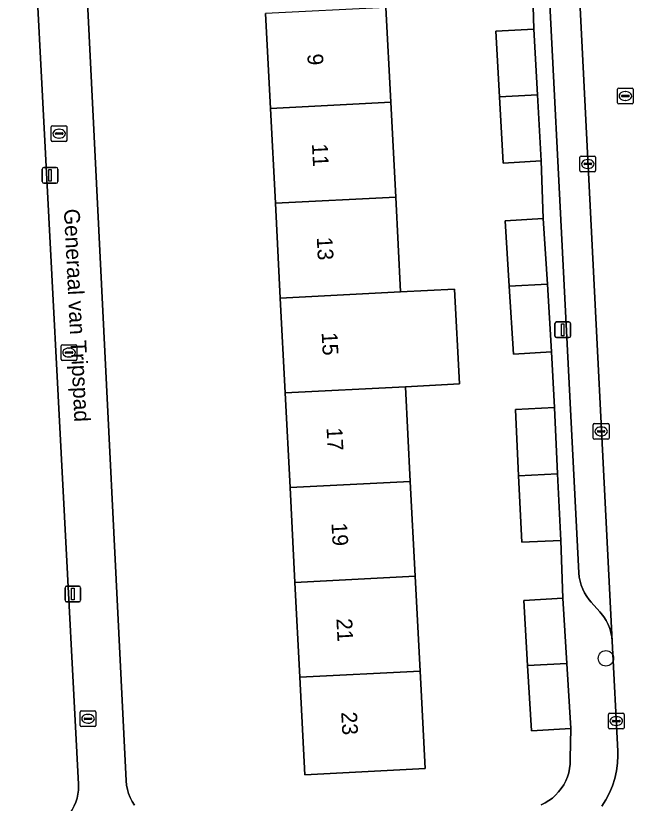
# Model space of a CAD drawing. Extents: x 161084 to 161928, y 385354 to 386522.
# Drawn here: x 161488.1 to 161527.4, y 385662.3 to 385712.5 of the extents above; entities that cross this region are included whole.
import ezdxf

# ---------------------------------------------------------------- set-up
doc = ezdxf.new("R2010")
doc.units = 0
for name, color, linetype in [('IMGEO_Boom', 7, 'Continuous'), ('IMGEO_Erf', 7, 'Continuous'), ('IMGEO_Kolk', 7, 'Continuous'), ('IMGEO_Lichtmast', 7, 'Continuous'), ('IMGEO_Openbare_ruimte_label', 7, 'Continuous'), ('IMGEO_Pand', 7, 'Continuous'), ('IMGEO_Pand_nummerreeks', 7, 'Continuous'), ('IMGEO_Parkeervlak_open', 7, 'Continuous'), ('IMGEO_Rijbaan_lokaal_open', 7, 'Continuous'), ('IMGEO_Rioolput', 7, 'Continuous'), ('IMGEO_Voetpad_open', 7, 'Continuous')]:
    doc.layers.add(name, color=color, linetype=linetype)

msp = doc.modelspace()

# ---------------------------------------------------------------- linework, layer by layer
at = {"layer": 'IMGEO_Boom'}
msp.add_circle((161525.652, 385671.57), 0.489, dxfattribs=at)
at = {"layer": 'IMGEO_Erf'}
for points in [[(161479.748, 385659.941), (161489.33, 385660.501), (161489.589, 385660.528), (161489.844, 385660.578), (161490.094, 385660.65), (161490.336, 385660.745), (161490.569, 385660.86), (161490.79, 385660.996), (161490.999, 385661.152), (161491.193, 385661.325), (161491.37, 385661.515), (161491.53, 385661.72), (161491.671, 385661.939), (161491.792, 385662.169), (161491.892, 385662.409), (161491.97, 385662.657), (161492.026, 385662.911), (161492.058, 385663.169), (161492.068, 385663.429), (161492.064, 385663.551), (161488.064, 385739.904)], [(161491.321, 385739.927), (161495.099, 385663.765), (161495.126, 385663.49), (161495.177, 385663.218), (161495.253, 385662.951), (161495.352, 385662.693), (161495.473, 385662.444), (161495.616, 385662.207)], [(161521.533, 385662.23), (161521.782, 385662.354), (161522.019, 385662.5), (161522.242, 385662.667), (161522.45, 385662.853), (161522.64, 385663.057), (161522.811, 385663.277), (161522.962, 385663.511), (161523.091, 385663.758), (161523.197, 385664.016), (161523.28, 385664.282), (161523.339, 385664.554), (161523.374, 385664.831), (161523.384, 385665.109), (161523.382, 385665.182), (161523.412, 385667.107), (161520.92, 385666.955), (161520.667, 385671.11), (161520.414, 385675.259), (161522.907, 385675.411), (161522.779, 385679.091), (161520.297, 385678.971), (161520.092, 385683.199), (161519.887, 385687.435), (161522.369, 385687.555), (161522.195, 385691.114), (161519.763, 385690.961), (161519.492, 385695.286), (161519.231, 385699.453), (161521.663, 385699.606), (161521.536, 385703.277), (161519.116, 385703.138), (161518.872, 385707.373), (161518.631, 385711.541), (161521.05, 385711.681), (161520.952, 385715.37)], [(161511.639, 385713.06), (161511.95, 385707.017), (161512.261, 385700.974), (161512.572, 385694.93), (161516.012, 385695.107), (161516.323, 385689.064), (161512.883, 385688.887), (161513.193, 385682.844), (161513.504, 385676.801), (161513.815, 385670.758), (161513.878, 385669.538), (161514.135, 385664.544), (161506.473, 385664.149), (161506.153, 385670.364), (161505.842, 385676.407), (161505.531, 385682.45), (161505.22, 385688.493), (161504.909, 385694.536), (161504.598, 385700.58), (161504.288, 385706.623), (161503.977, 385712.666)]]:
    msp.add_lwpolyline(points, dxfattribs=at)
at = {"layer": 'IMGEO_Kolk'}
for p, q in [((161523.997, 385702.658), (161523.997, 385703.51)), ((161524.072, 385703.584), (161524.924, 385703.584)), ((161524.485, 385703.364), (161524.51, 385703.364)), ((161524.998, 385703.51), (161524.998, 385702.658)), ((161524.256, 385703.078), (161524.256, 385703.09)), ((161524.694, 385703.041), (161524.296, 385703.041)), ((161524.299, 385703.127), (161524.697, 385703.127)), ((161524.508, 385702.804), (161524.483, 385702.804)), ((161524.74, 385703.09), (161524.74, 385703.078)), ((161524.924, 385702.584), (161524.072, 385702.584)), ((161490.958, 385690.636), (161490.958, 385691.488)), ((161491.033, 385691.562), (161491.885, 385691.562)), ((161491.446, 385691.342), (161491.471, 385691.342)), ((161491.959, 385691.488), (161491.959, 385690.636)), ((161491.217, 385691.056), (161491.217, 385691.068)), ((161491.655, 385691.019), (161491.257, 385691.019)), ((161491.26, 385691.105), (161491.658, 385691.105)), ((161491.469, 385690.782), (161491.444, 385690.782)), ((161491.701, 385691.068), (161491.701, 385691.056)), ((161491.885, 385690.562), (161491.033, 385690.562)), ((161524.848, 385685.607), (161524.848, 385686.459)), ((161524.923, 385686.533), (161525.775, 385686.533)), ((161525.336, 385686.313), (161525.361, 385686.313)), ((161525.849, 385686.459), (161525.849, 385685.607)), ((161525.107, 385686.027), (161525.107, 385686.039)), ((161525.545, 385685.99), (161525.147, 385685.99)), ((161525.15, 385686.076), (161525.548, 385686.076)), ((161525.359, 385685.753), (161525.334, 385685.753)), ((161525.591, 385686.039), (161525.591, 385686.027)), ((161525.775, 385685.533), (161524.923, 385685.533)), ((161492.167, 385667.292), (161492.167, 385668.144)), ((161492.242, 385668.218), (161493.094, 385668.218)), ((161493.168, 385668.144), (161493.168, 385667.292)), ((161525.883, 385668.071), (161526.735, 385668.071)), ((161492.426, 385667.712), (161492.426, 385667.724)), ((161492.864, 385667.675), (161492.466, 385667.675)), ((161492.469, 385667.761), (161492.867, 385667.761)), ((161492.655, 385667.998), (161492.68, 385667.998)), ((161492.91, 385667.724), (161492.91, 385667.712)), ((161525.808, 385667.145), (161525.808, 385667.997)), ((161526.067, 385667.565), (161526.067, 385667.577)), ((161526.11, 385667.614), (161526.508, 385667.614)), ((161526.296, 385667.851), (161526.321, 385667.851)), ((161526.551, 385667.577), (161526.551, 385667.565)), ((161526.809, 385667.997), (161526.809, 385667.145)), ((161493.094, 385667.218), (161492.242, 385667.218)), ((161492.678, 385667.438), (161492.653, 385667.438)), ((161526.735, 385667.071), (161525.883, 385667.071)), ((161526.505, 385667.528), (161526.107, 385667.528)), ((161526.319, 385667.291), (161526.294, 385667.291))]:
    msp.add_line(p, q, dxfattribs=at)
for points in [[(161523.997, 385702.658), (161523.997, 385703.51)], [(161524.072, 385703.584), (161524.924, 385703.584)], [(161524.998, 385703.51), (161524.998, 385702.658)], [(161524.924, 385702.584), (161524.072, 385702.584)], [(161490.958, 385690.636), (161490.958, 385691.488)], [(161491.033, 385691.562), (161491.885, 385691.562)], [(161491.959, 385691.488), (161491.959, 385690.636)], [(161491.885, 385690.562), (161491.033, 385690.562)], [(161524.848, 385685.607), (161524.848, 385686.459)], [(161524.923, 385686.533), (161525.775, 385686.533)], [(161525.849, 385686.459), (161525.849, 385685.607)], [(161525.775, 385685.533), (161524.923, 385685.533)], [(161492.167, 385667.292), (161492.167, 385668.144)], [(161492.242, 385668.218), (161493.094, 385668.218)], [(161493.168, 385668.144), (161493.168, 385667.292)], [(161525.883, 385668.071), (161526.735, 385668.071)], [(161525.808, 385667.145), (161525.808, 385667.997)], [(161526.809, 385667.997), (161526.809, 385667.145)], [(161493.094, 385667.218), (161492.242, 385667.218)], [(161526.735, 385667.071), (161525.883, 385667.071)]]:
    msp.add_lwpolyline(points, dxfattribs=at)
for centre, radius, start, end in [((161524.074, 385703.508), 0.0765, 91.552, 178.448), ((161524.074, 385703.508), 0.0765, 91.552, 178.448), ((161524.922, 385703.508), 0.0765, 1.552, 88.448), ((161524.922, 385703.508), 0.0765, 1.552, 88.448), ((161524.296, 385703.087), 0.0403, 85.8775, 175.7526), ((161524.293, 385703.077), 0.0366, 178.938, 274.7102), ((161524.697, 385703.084), 0.043, 264.8664, 352.4533), ((161524.701, 385703.089), 0.0386, 1.7309, 96.639), ((161524.074, 385702.66), 0.0765, 181.552, 268.448), ((161524.074, 385702.66), 0.0765, 181.552, 268.448), ((161524.922, 385702.66), 0.0765, 271.552, 358.448), ((161524.922, 385702.66), 0.0765, 271.552, 358.448), ((161491.035, 385691.486), 0.0765, 91.552, 178.448), ((161491.035, 385691.486), 0.0765, 91.552, 178.448), ((161491.883, 385691.486), 0.0765, 1.552, 88.448), ((161491.883, 385691.486), 0.0765, 1.552, 88.448), ((161491.035, 385690.638), 0.0765, 181.552, 268.448), ((161491.035, 385690.638), 0.0765, 181.552, 268.448), ((161491.257, 385691.065), 0.0403, 85.8775, 175.7526), ((161491.254, 385691.055), 0.0366, 178.938, 274.7102), ((161491.658, 385691.062), 0.043, 264.8664, 352.4533), ((161491.662, 385691.067), 0.0386, 1.7309, 96.639), ((161491.883, 385690.638), 0.0765, 271.552, 358.448), ((161491.883, 385690.638), 0.0765, 271.552, 358.448), ((161524.925, 385686.457), 0.0765, 91.552, 178.448), ((161524.925, 385686.457), 0.0765, 91.552, 178.448), ((161525.773, 385686.457), 0.0765, 1.552, 88.448), ((161525.773, 385686.457), 0.0765, 1.552, 88.448), ((161525.147, 385686.036), 0.0403, 85.8775, 175.7526), ((161525.144, 385686.026), 0.0366, 178.938, 274.7102), ((161525.548, 385686.033), 0.043, 264.8664, 352.4533), ((161525.552, 385686.038), 0.0386, 1.7309, 96.639), ((161524.925, 385685.609), 0.0765, 181.552, 268.448), ((161524.925, 385685.609), 0.0765, 181.552, 268.448), ((161525.773, 385685.609), 0.0765, 271.552, 358.448), ((161525.773, 385685.609), 0.0765, 271.552, 358.448), ((161492.244, 385668.142), 0.0765, 91.552, 178.448), ((161492.244, 385668.142), 0.0765, 91.552, 178.448), ((161493.092, 385668.142), 0.0765, 1.552, 88.448), ((161493.092, 385668.142), 0.0765, 1.552, 88.448), ((161525.885, 385667.995), 0.0765, 91.552, 178.448), ((161525.885, 385667.995), 0.0765, 91.552, 178.448), ((161526.733, 385667.995), 0.0765, 1.552, 88.448), ((161526.733, 385667.995), 0.0765, 1.552, 88.448), ((161492.466, 385667.721), 0.0403, 85.8775, 175.7526), ((161492.463, 385667.711), 0.0366, 178.938, 274.7102), ((161492.867, 385667.718), 0.043, 264.8664, 352.4533), ((161492.871, 385667.723), 0.0386, 1.7309, 96.639), ((161526.107, 385667.574), 0.0403, 85.8775, 175.7526), ((161526.104, 385667.564), 0.0366, 178.938, 274.7102), ((161526.508, 385667.571), 0.043, 264.8664, 352.4533), ((161526.512, 385667.576), 0.0386, 1.7309, 96.639), ((161492.244, 385667.294), 0.0765, 181.552, 268.448), ((161492.244, 385667.294), 0.0765, 181.552, 268.448), ((161493.092, 385667.294), 0.0765, 271.552, 358.448), ((161493.092, 385667.294), 0.0765, 271.552, 358.448), ((161525.885, 385667.147), 0.0765, 181.552, 268.448), ((161525.885, 385667.147), 0.0765, 181.552, 268.448), ((161526.733, 385667.147), 0.0765, 271.552, 358.448), ((161526.733, 385667.147), 0.0765, 271.552, 358.448)]:
    msp.add_arc(centre, radius, start, end, dxfattribs=at)
for centre, major_axis, ratio, start_param, end_param in [((161524.484, 385703.084), (-0.387, 0.002), 0.722429, 4.712389, 7.853982), ((161524.509, 385703.084), (-0.39, 0.002), 0.717154, 1.570796, 4.712389), ((161491.445, 385691.062), (-0.387, 0.002), 0.722429, 4.712389, 7.853982), ((161491.47, 385691.062), (-0.39, 0.002), 0.717154, 1.570796, 4.712389), ((161525.335, 385686.033), (-0.387, 0.002), 0.722429, 4.712389, 7.853982), ((161525.36, 385686.033), (-0.39, 0.002), 0.717154, 1.570796, 4.712389), ((161492.654, 385667.718), (-0.387, 0.002), 0.722429, 4.712389, 7.853982), ((161492.679, 385667.718), (-0.39, 0.002), 0.717154, 1.570796, 4.712389), ((161526.295, 385667.571), (-0.387, 0.002), 0.722429, 4.712389, 7.853982), ((161526.32, 385667.571), (-0.39, 0.002), 0.717154, 1.570796, 4.712389)]:
    msp.add_ellipse(centre, major_axis=major_axis, ratio=ratio, start_param=start_param, end_param=end_param, dxfattribs=at)
at = {"layer": 'IMGEO_Lichtmast'}
for p, q in [((161489.752, 385701.96), (161489.752, 385702.76)), ((161489.752, 385702.76), (161489.752, 385701.96)), ((161489.852, 385702.86), (161490.642, 385702.86)), ((161490.642, 385702.86), (161489.852, 385702.86)), ((161490.742, 385702.76), (161490.742, 385701.96)), ((161490.742, 385701.96), (161490.742, 385702.76)), ((161490.642, 385701.86), (161489.852, 385701.86)), ((161489.852, 385701.86), (161490.642, 385701.86)), ((161522.404, 385692.112), (161522.404, 385692.912)), ((161522.404, 385692.912), (161522.404, 385692.112)), ((161522.504, 385693.012), (161523.294, 385693.012)), ((161523.294, 385693.012), (161522.504, 385693.012)), ((161523.394, 385692.912), (161523.394, 385692.112)), ((161523.394, 385692.112), (161523.394, 385692.912)), ((161523.294, 385692.012), (161522.504, 385692.012)), ((161522.504, 385692.012), (161523.294, 385692.012)), ((161491.204, 385675.273), (161491.204, 385676.073)), ((161491.204, 385676.073), (161491.204, 385675.273)), ((161491.304, 385676.173), (161492.094, 385676.173)), ((161492.094, 385676.173), (161491.304, 385676.173)), ((161492.194, 385676.073), (161492.194, 385675.273)), ((161492.194, 385675.273), (161492.194, 385676.073)), ((161492.094, 385675.173), (161491.304, 385675.173)), ((161491.304, 385675.173), (161492.094, 385675.173))]:
    msp.add_line(p, q, dxfattribs=at)
for points in [[(161490.172, 385702.735), (161490.322, 385702.735), (161490.322, 385701.985), (161490.172, 385701.985), (161490.172, 385702.735)], [(161522.824, 385692.887), (161522.974, 385692.887), (161522.974, 385692.137), (161522.824, 385692.137), (161522.824, 385692.887)], [(161491.624, 385676.048), (161491.774, 385676.048), (161491.774, 385675.298), (161491.624, 385675.298), (161491.624, 385676.048)]]:
    msp.add_lwpolyline(points, dxfattribs=at)
for centre, start, end in [((161489.852, 385702.76), 90, 180), ((161489.852, 385702.76), 90, 180), ((161490.642, 385702.76), 0, 90), ((161490.642, 385702.76), 360, 90), ((161489.852, 385701.96), 180, 270), ((161489.852, 385701.96), 180, 270), ((161490.642, 385701.96), 270, 0), ((161490.642, 385701.96), 270, 0), ((161522.504, 385692.912), 90, 180), ((161522.504, 385692.912), 90, 180), ((161523.294, 385692.912), 0, 90), ((161523.294, 385692.912), 360, 90), ((161522.504, 385692.112), 180, 270), ((161522.504, 385692.112), 180, 270), ((161523.294, 385692.112), 270, 0), ((161523.294, 385692.112), 270, 0), ((161491.304, 385676.073), 90, 180), ((161491.304, 385676.073), 90, 180), ((161492.094, 385676.073), 0, 90), ((161492.094, 385676.073), 360, 90), ((161491.304, 385675.273), 180, 270), ((161491.304, 385675.273), 180, 270), ((161492.094, 385675.273), 270, 0), ((161492.094, 385675.273), 270, 0)]:
    msp.add_arc(centre, 0.1, start, end, dxfattribs=at)
at = {"layer": 'IMGEO_Pand'}
for points in [[(161503.977, 385712.666), (161504.288, 385706.623), (161511.95, 385707.017), (161511.639, 385713.06)], [(161521.05, 385711.681), (161518.631, 385711.541), (161518.872, 385707.373), (161521.292, 385707.497)], [(161521.292, 385707.497), (161518.872, 385707.373), (161519.116, 385703.138), (161521.536, 385703.277)], [(161512.261, 385700.974), (161511.95, 385707.017), (161504.288, 385706.623), (161504.598, 385700.58)], [(161512.572, 385694.93), (161512.261, 385700.974), (161504.598, 385700.58), (161504.909, 385694.536)], [(161521.663, 385699.606), (161519.231, 385699.453), (161519.492, 385695.286), (161521.926, 385695.411)], [(161521.926, 385695.411), (161519.492, 385695.286), (161519.763, 385690.961), (161522.195, 385691.114)], [(161512.572, 385694.93), (161504.909, 385694.536), (161505.22, 385688.493), (161512.883, 385688.887), (161516.323, 385689.064), (161516.012, 385695.107)], [(161513.193, 385682.844), (161512.883, 385688.887), (161505.22, 385688.493), (161505.531, 385682.45)], [(161522.369, 385687.555), (161519.887, 385687.435), (161520.092, 385683.199), (161522.574, 385683.326)], [(161522.574, 385683.326), (161520.092, 385683.199), (161520.297, 385678.971), (161522.779, 385679.091)], [(161505.531, 385682.45), (161505.842, 385676.407), (161513.504, 385676.801), (161513.193, 385682.844)], [(161513.815, 385670.758), (161513.504, 385676.801), (161505.842, 385676.407), (161506.153, 385670.364)], [(161522.907, 385675.411), (161520.414, 385675.259), (161520.667, 385671.11), (161523.161, 385671.239)], [(161523.161, 385671.239), (161520.667, 385671.11), (161520.92, 385666.955), (161523.412, 385667.107)], [(161506.153, 385670.364), (161506.473, 385664.149), (161514.135, 385664.544), (161513.878, 385669.538), (161513.815, 385670.758)]]:
    msp.add_lwpolyline(points, close=True, dxfattribs=at)
at = {"layer": 'IMGEO_Parkeervlak_open'}
msp.add_lwpolyline([(161521.026, 385734.119), (161523.932, 385677.02), (161523.958, 385676.753), (161524.007, 385676.489), (161524.08, 385676.231), (161524.175, 385675.98), (161524.293, 385675.739), (161524.431, 385675.509), (161524.59, 385675.293), (161524.704, 385675.159), (161525.273, 385674.531), (161525.357, 385674.434), (161525.522, 385674.214), (161525.667, 385673.981), (161525.791, 385673.735), (161525.892, 385673.479), (161525.97, 385673.216), (161526.024, 385672.946), (161526.054, 385672.673), (161522.77, 385737.447)], dxfattribs=at)
at = {"layer": 'IMGEO_Rijbaan_lokaal_open'}
msp.add_lwpolyline([(161522.77, 385737.447), (161526.054, 385672.673), (161526.41, 385665.649), (161526.417, 385665.382), (161526.397, 385664.889), (161526.333, 385664.4), (161526.225, 385663.919), (161526.075, 385663.449), (161525.883, 385662.994), (161525.652, 385662.559), (161525.382, 385662.146)], dxfattribs=at)
at = {"layer": 'IMGEO_Rioolput'}
for p, q in [((161526.39, 385706.99), (161526.39, 385707.842)), ((161526.465, 385707.916), (161527.317, 385707.916)), ((161527.391, 385707.842), (161527.391, 385706.99)), ((161526.649, 385707.41), (161526.649, 385707.422)), ((161527.087, 385707.373), (161526.689, 385707.373)), ((161526.692, 385707.459), (161527.09, 385707.459)), ((161526.878, 385707.696), (161526.903, 385707.696)), ((161527.133, 385707.422), (161527.133, 385707.41)), ((161527.317, 385706.916), (161526.465, 385706.916)), ((161526.901, 385707.136), (161526.876, 385707.136)), ((161490.326, 385704.592), (161490.326, 385705.444)), ((161490.401, 385705.518), (161491.253, 385705.518)), ((161490.814, 385705.298), (161490.839, 385705.298)), ((161491.327, 385705.444), (161491.327, 385704.592)), ((161490.585, 385705.012), (161490.585, 385705.024)), ((161491.023, 385704.975), (161490.625, 385704.975)), ((161490.628, 385705.061), (161491.026, 385705.061)), ((161490.837, 385704.738), (161490.812, 385704.738)), ((161491.069, 385705.024), (161491.069, 385705.012)), ((161491.253, 385704.518), (161490.401, 385704.518))]:
    msp.add_line(p, q, dxfattribs=at)
for points in [[(161526.39, 385706.99), (161526.39, 385707.842)], [(161526.465, 385707.916), (161527.317, 385707.916)], [(161527.391, 385707.842), (161527.391, 385706.99)], [(161527.317, 385706.916), (161526.465, 385706.916)], [(161490.326, 385704.592), (161490.326, 385705.444)], [(161490.401, 385705.518), (161491.253, 385705.518)], [(161491.327, 385705.444), (161491.327, 385704.592)], [(161491.253, 385704.518), (161490.401, 385704.518)]]:
    msp.add_lwpolyline(points, dxfattribs=at)
for centre, radius, start, end in [((161526.467, 385707.84), 0.0765, 91.552, 178.448), ((161526.467, 385707.84), 0.0765, 91.552, 178.448), ((161527.315, 385707.84), 0.0765, 1.552, 88.448), ((161527.315, 385707.84), 0.0765, 1.552, 88.448), ((161526.689, 385707.419), 0.0403, 85.8775, 175.7526), ((161526.686, 385707.409), 0.0366, 178.938, 274.7102), ((161527.09, 385707.416), 0.043, 264.8664, 352.4533), ((161527.094, 385707.421), 0.0386, 1.7309, 96.639), ((161526.467, 385706.992), 0.0765, 181.552, 268.448), ((161526.467, 385706.992), 0.0765, 181.552, 268.448), ((161527.315, 385706.992), 0.0765, 271.552, 358.448), ((161527.315, 385706.992), 0.0765, 271.552, 358.448), ((161490.403, 385705.442), 0.0765, 91.552, 178.448), ((161490.403, 385705.442), 0.0765, 91.552, 178.448), ((161491.251, 385705.442), 0.0765, 1.552, 88.448), ((161491.251, 385705.442), 0.0765, 1.552, 88.448), ((161490.625, 385705.021), 0.0403, 85.8775, 175.7526), ((161490.622, 385705.011), 0.0366, 178.938, 274.7102), ((161491.026, 385705.018), 0.043, 264.8664, 352.4533), ((161491.03, 385705.023), 0.0386, 1.7309, 96.639), ((161490.403, 385704.594), 0.0765, 181.552, 268.448), ((161490.403, 385704.594), 0.0765, 181.552, 268.448), ((161491.251, 385704.594), 0.0765, 271.552, 358.448), ((161491.251, 385704.594), 0.0765, 271.552, 358.448)]:
    msp.add_arc(centre, radius, start, end, dxfattribs=at)
for centre, major_axis, ratio, start_param, end_param in [((161526.877, 385707.416), (-0.387, 0.002), 0.722429, 4.712389, 7.853982), ((161526.902, 385707.416), (-0.39, 0.002), 0.717154, 1.570796, 4.712389), ((161490.813, 385705.018), (-0.387, 0.002), 0.722429, 4.712389, 7.853982), ((161490.838, 385705.018), (-0.39, 0.002), 0.717154, 1.570796, 4.712389)]:
    msp.add_ellipse(centre, major_axis=major_axis, ratio=ratio, start_param=start_param, end_param=end_param, dxfattribs=at)
at = {"layer": 'IMGEO_Voetpad_open'}
for points in [[(161488.064, 385739.904), (161492.064, 385663.551), (161492.068, 385663.429), (161492.058, 385663.169), (161492.026, 385662.911), (161491.97, 385662.657), (161491.892, 385662.409), (161491.792, 385662.169)], [(161495.616, 385662.207), (161495.473, 385662.444), (161495.352, 385662.693), (161495.253, 385662.951), (161495.177, 385663.218), (161495.126, 385663.49), (161495.099, 385663.765), (161491.321, 385739.927)], [(161525.382, 385662.146), (161525.652, 385662.559), (161525.883, 385662.994), (161526.075, 385663.449), (161526.225, 385663.919), (161526.333, 385664.4), (161526.397, 385664.889), (161526.417, 385665.382), (161526.41, 385665.649), (161526.054, 385672.673), (161526.024, 385672.946), (161525.97, 385673.216), (161525.892, 385673.479), (161525.791, 385673.735), (161525.667, 385673.981), (161525.522, 385674.214), (161525.357, 385674.434), (161525.273, 385674.531), (161524.704, 385675.159), (161524.59, 385675.293), (161524.431, 385675.509), (161524.293, 385675.739), (161524.175, 385675.98), (161524.08, 385676.231), (161524.007, 385676.489), (161523.958, 385676.753), (161523.932, 385677.02), (161521.026, 385734.119)], [(161520.952, 385715.37), (161521.05, 385711.681), (161521.292, 385707.497), (161521.536, 385703.277), (161521.663, 385699.606), (161521.926, 385695.411), (161522.195, 385691.114), (161522.369, 385687.555), (161522.574, 385683.326), (161522.779, 385679.091), (161522.907, 385675.411), (161523.161, 385671.239), (161523.412, 385667.107), (161523.382, 385665.182), (161523.384, 385665.109), (161523.374, 385664.831), (161523.339, 385664.554), (161523.28, 385664.282), (161523.197, 385664.016), (161523.091, 385663.758), (161522.962, 385663.511), (161522.811, 385663.277), (161522.64, 385663.057), (161522.45, 385662.853), (161522.242, 385662.667), (161522.019, 385662.5), (161521.782, 385662.354), (161521.533, 385662.23)]]:
    msp.add_lwpolyline(points, dxfattribs=at)

# ---------------------------------------------------------------- texts
at = {"layer": 'IMGEO_Openbare_ruimte_label'}
msp.add_text('Generaal van Tripspad', height=1, rotation=272.8653, dxfattribs=at).set_placement((161491.128, 385700.205))
at = {"layer": 'IMGEO_Pand_nummerreeks'}
for s, rotation, p in [('9', 272.9455, (161506.632, 385710.091)), ('11', 272.9455, (161506.927, 385704.365)), ('13', 272.9455, (161507.234, 385698.408)), ('15', 272.9448, (161507.546, 385692.336)), ('17', 272.9455, (161507.859, 385686.264)), ('19', 272.9455, (161508.171, 385680.192)), ('21', 272.9455, (161508.485, 385674.099)), ('23', 272.9455, (161508.791, 385668.14))]:
    msp.add_text(s, height=1, rotation=rotation, dxfattribs=at).set_placement(p)

doc.saveas('drawing.dxf')
